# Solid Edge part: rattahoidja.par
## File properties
Author: Romil
Template: iso part.par
Last saved by: Romil
Revision: 39
Application: Solid Edge
Accuracy: 0.990
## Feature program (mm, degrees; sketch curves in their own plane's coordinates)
sketch for "unnamed Protrusion 1" plane through (0, 0, 0) normal (1, 0, 0) x-axis (0, 1, 0)
  line (14.405, 7.625) -> (-22.495, 7.625)
  line (-22.495, -7.625) -> (14.405, -7.625)
  line (14.405, -7.625) -> (26.6848, -4.0309)
  line (14.405, 7.625) -> (26.6848, 4.0309)
extrude "unnamed Protrusion 1" add finite 7.8 symmetric
sketch for "ExtrudedCutout_11" #1 plane through (0, 0, 0) normal (1, 0, 0) x-axis (0, 1, 0)
sketch for "ExtrudedCutout_11" #2 plane through (0, 0, 0) normal (1, 0, 0) x-axis (0, 1, 0)
sketch for "ExtrudedCutout_11" #3 plane through (0, 0, 0) normal (1, 0, 0) x-axis (0, 1, 0)
  line (-19.5748, 2.1053) -> (-16.4143, 3.518)
  line (-19.5748, -2.1053) -> (-16.4143, -3.518)
sketch for "ExtrudedCutout_11" #4 plane through (0, 0, 0) normal (1, 0, 0) x-axis (0, 1, 0)
  line (-16.2756, 2.78) -> (-19.2092, 1.4708)
  arc centre (-22.495, 0) radius 3.6 from (-19.2092, 1.4708) to (-19.2076, -1.4673) cw
  line (-19.2076, -1.4673) -> (-16.2754, -2.78)
  line (-16.0435, -2.78) -> (-16.2754, -2.78)
  arc centre (-22.495, 0) radius 7.025 from (-16.0435, 2.78) to (-16.0435, -2.78) cw
  line (-16.0435, 2.78) -> (-16.2756, 2.78)
sketch for "ExtrudedCutout_11" #5 plane through (0, 0, 0) normal (1, 0, 0) x-axis (0, 1, 0)
  arc centre (-22.495, 0) radius 7.625 from (-15.3948, 2.78) to (-15.3948, -2.78) cw
  line (-15.3948, -2.78) -> (-13.488, -2.78)
  arc centre (-20.5881, 0) radius 7.625 from (-13.488, 2.78) to (-13.488, -2.78) cw
  line (-15.3948, 2.78) -> (-13.488, 2.78)
sketch for "ExtrudedCutout_11" #6 plane through (0, 0, 0) normal (1, 0, 0) x-axis (0, 1, 0)
  line (-11.5918, -2.4) -> (1.505, -2.4)
  line (1.505, 2.4) -> (-11.5918, 2.4)
sketch for "ExtrudedCutout_11" #7 plane through (0, 0, 0) normal (1, 0, 0) x-axis (0, 1, 0)
  line (-6.745, 3.6) -> (-14.245, 3.6)
  line (-14.245, 3.6) -> (-14.245, 7.025)
  line (-14.245, 7.025) -> (-6.745, 7.025)
  line (-6.745, 3.6) -> (-6.745, 7.025)
sketch for "ExtrudedCutout_11" #8 plane through (0, 0, 0) normal (1, 0, 0) x-axis (0, 1, 0)
  line (-14.745, 3.6) -> (-15.7733, 3.6)
  arc centre (-22.495, 0) radius 7.625 from (-19.5302, 7.025) to (-15.7733, 3.6) cw
  line (-19.5302, 7.025) -> (-14.745, 7.025)
  line (-14.745, 7.025) -> (-14.745, 3.6)
sketch for "ExtrudedCutout_11" #9 plane through (0, 0, 0) normal (1, 0, 0) x-axis (0, 1, 0)
  line (1.255, 3.6) -> (-6.245, 3.6)
  line (-6.245, 7.025) -> (-6.245, 3.6)
  line (-6.245, 7.025) -> (1.255, 7.025)
  line (1.255, 3.6) -> (1.255, 7.025)
sketch for "ExtrudedCutout_11" #10 plane through (0, 0, 0) normal (1, 0, 0) x-axis (0, 1, 0)
  line (9.255, 3.6) -> (1.755, 3.6)
  line (1.755, 7.025) -> (1.755, 3.6)
  line (1.755, 7.025) -> (9.255, 7.025)
  line (9.255, 3.6) -> (9.255, 7.025)
sketch for "ExtrudedCutout_11" #11 plane through (0, 0, 0) normal (1, 0, 0) x-axis (0, 1, 0)
  line (17.255, 3.6) -> (9.755, 3.6)
  line (9.755, 7.025) -> (9.755, 3.6)
  line (9.755, 7.025) -> (14.405, 7.025)
  line (14.405, 7.025) -> (17.255, 6.1849)
  line (17.255, 3.6) -> (17.255, 6.1849)
sketch for "ExtrudedCutout_11" #12 plane through (0, 0, 0) normal (1, 0, 0) x-axis (0, 1, 0)
  line (17.755, 3.6) -> (25.255, 3.6)
  line (25.255, 3.8268) -> (25.255, 3.6)
  line (17.755, 6.0376) -> (25.255, 3.8268)
  line (17.755, 6.0376) -> (17.755, 3.6)
sketch for "ExtrudedCutout_11" #13 plane through (0, 0, 0) normal (1, 0, 0) x-axis (0, 1, 0)
  arc centre (24.53, 0.975) radius 0.1 from (24.63, 0.975) to (24.53, 0.875) cw
  line (24.53, 0.875) -> (23.4601, 0.875)
  line (23.4601, 0.875) -> (22.4213, 0.875)
  arc centre (22.4213, 1.175) radius 0.3 from (22.1409, 1.2818) to (22.4213, 0.875) ccw
  arc centre (25.505, 0) radius 3.6 from (22.1409, 1.2818) to (22.7266, 2.2892) cw
  arc centre (22.4951, 2.48) radius 0.3 from (22.7266, 2.2892) to (22.4951, 2.78) ccw
  line (20.5552, 2.78) -> (22.4951, 2.78)
  arc centre (20.5552, 2.48) radius 0.3 from (20.5552, 2.78) to (20.3237, 2.2892) ccw
  arc centre (20.5552, -2.48) radius 0.3 from (20.3237, -2.2892) to (20.5552, -2.78) ccw
  line (20.5552, -2.78) -> (22.4951, -2.78)
  arc centre (22.4951, -2.48) radius 0.3 from (22.4951, -2.78) to (22.7266, -2.2892) ccw
  arc centre (25.505, 0) radius 3.6 from (22.7266, -2.2892) to (22.1409, -1.2818) cw
  arc centre (22.4213, -1.175) radius 0.3 from (22.4213, -0.875) to (22.1409, -1.2818) ccw
  line (22.4213, -0.875) -> (23.4601, -0.875)
  line (23.4601, -0.875) -> (24.53, -0.875)
  arc centre (24.53, -0.975) radius 0.1 from (24.53, -0.875) to (24.63, -0.975) cw
  line (24.63, -0.975) -> (24.63, -2.0449)
  line (24.63, -2.0449) -> (24.63, -2.181)
  arc centre (25.505, 0) radius 2.35 from (24.63, -2.181) to (26.38, -2.181) ccw
  line (26.38, -2.181) -> (26.38, -2.0449)
  line (26.38, -2.0449) -> (26.38, -0.975)
  arc centre (26.48, -0.975) radius 0.1 from (26.38, -0.975) to (26.48, -0.875) cw
  line (26.48, -0.875) -> (27.5499, -0.875)
  line (27.5499, -0.875) -> (27.686, -0.875)
  arc centre (25.505, 0) radius 2.35 from (27.686, -0.875) to (27.686, 0.875) ccw
  line (27.686, 0.875) -> (27.5499, 0.875)
  line (27.5499, 0.875) -> (26.48, 0.875)
  arc centre (26.48, 0.975) radius 0.1 from (26.48, 0.875) to (26.38, 0.975) cw
  line (26.38, 0.975) -> (26.38, 2.0449)
  line (26.38, 2.0449) -> (26.38, 2.181)
  arc centre (25.505, 0) radius 2.35 from (26.38, 2.181) to (24.63, 2.181) ccw
  line (24.63, 2.181) -> (24.63, 2.0449)
  line (24.63, 2.0449) -> (24.63, 0.975)
sketch for "ExtrudedCutout_11" #14 plane through (0, 0, 0) normal (1, 0, 0) x-axis (0, 1, 0)
  circle centre (17.505, 0) radius 2.4
sketch for "ExtrudedCutout_11" #15 plane through (0, 0, 0) normal (1, 0, 0) x-axis (0, 1, 0)
  arc centre (17.5453, 0) radius 3.6 from (14.7669, -2.2892) to (14.7669, 2.2892) cw
  arc centre (14.5354, 2.48) radius 0.3 from (14.7669, 2.2892) to (14.5354, 2.78) ccw
  line (12.5149, 2.78) -> (14.5354, 2.78)
  arc centre (12.5149, 2.48) radius 0.3 from (12.5149, 2.78) to (12.2834, 2.2892) ccw
  arc centre (9.505, 0) radius 3.6 from (12.2834, 2.2892) to (12.8691, 1.2818) cw
  arc centre (12.5887, 1.175) radius 0.3 from (12.5887, 0.875) to (12.8691, 1.2818) ccw
  line (12.5887, 0.875) -> (11.5499, 0.875)
  line (11.5499, 0.875) -> (10.48, 0.875)
  arc centre (10.48, 0.975) radius 0.1 from (10.48, 0.875) to (10.38, 0.975) cw
  line (10.38, 0.975) -> (10.38, 2.0449)
  line (10.38, 2.0449) -> (10.38, 2.181)
  arc centre (9.505, 0) radius 2.35 from (10.38, 2.181) to (8.63, 2.181) ccw
  line (8.63, 2.181) -> (8.63, 2.0449)
  line (8.63, 2.0449) -> (8.63, 0.975)
  arc centre (8.53, 0.975) radius 0.1 from (8.63, 0.975) to (8.53, 0.875) cw
  line (8.53, 0.875) -> (7.4601, 0.875)
  line (7.4601, 0.875) -> (7.324, 0.875)
  arc centre (9.505, 0) radius 2.35 from (7.324, 0.875) to (7.324, -0.875) ccw
  line (7.324, -0.875) -> (7.4601, -0.875)
  line (7.4601, -0.875) -> (8.53, -0.875)
  arc centre (8.53, -0.975) radius 0.1 from (8.53, -0.875) to (8.63, -0.975) cw
  line (8.63, -0.975) -> (8.63, -2.0449)
  line (8.63, -2.0449) -> (8.63, -2.181)
  arc centre (9.505, 0) radius 2.35 from (8.63, -2.181) to (10.38, -2.181) ccw
  line (10.38, -2.181) -> (10.38, -2.0449)
  line (10.38, -2.0449) -> (10.38, -0.975)
  arc centre (10.48, -0.975) radius 0.1 from (10.38, -0.975) to (10.48, -0.875) cw
  line (10.48, -0.875) -> (11.5499, -0.875)
  line (11.5499, -0.875) -> (12.5887, -0.875)
  arc centre (12.5887, -1.175) radius 0.3 from (12.8691, -1.2818) to (12.5887, -0.875) ccw
  arc centre (9.505, 0) radius 3.6 from (12.8691, -1.2818) to (12.2834, -2.2892) cw
  arc centre (12.5149, -2.48) radius 0.3 from (12.2834, -2.2892) to (12.5149, -2.78) ccw
  line (12.5149, -2.78) -> (14.5354, -2.78)
  arc centre (14.5354, -2.48) radius 0.3 from (14.5354, -2.78) to (14.7669, -2.2892) ccw
sketch for "ExtrudedCutout_11" #16 plane through (0, 0, 0) normal (1, 0, 0) x-axis (0, 1, 0)
  arc centre (6.4951, 2.48) radius 0.3 from (6.7266, 2.2892) to (6.4951, 2.78) ccw
  line (6.4951, 2.78) -> (4.5149, 2.78)
  arc centre (4.5149, 2.48) radius 0.3 from (4.5149, 2.78) to (4.2834, 2.2892) ccw
  arc centre (4.5149, -2.48) radius 0.3 from (4.2834, -2.2892) to (4.5149, -2.78) ccw
  line (6.4951, -2.78) -> (4.5149, -2.78)
  arc centre (6.4951, -2.48) radius 0.3 from (6.4951, -2.78) to (6.7266, -2.2892) ccw
sketch for "ExtrudedCutout_11" #17 plane through (0, 0, 0) normal (1, 0, 0) x-axis (0, 1, 0)
  line (9.255, -7.025) -> (9.255, -3.6)
  line (1.755, -3.6) -> (9.255, -3.6)
  line (1.755, -3.6) -> (1.755, -7.025)
  line (1.755, -7.025) -> (9.255, -7.025)
sketch for "ExtrudedCutout_11" #18 plane through (0, 0, 0) normal (1, 0, 0) x-axis (0, 1, 0)
  line (9.755, -3.6) -> (17.255, -3.6)
  line (17.255, -6.1849) -> (17.255, -3.6)
  line (14.405, -7.025) -> (17.255, -6.1849)
  line (9.755, -7.025) -> (14.405, -7.025)
  line (9.755, -3.6) -> (9.755, -7.025)
sketch for "ExtrudedCutout_11" #19 plane through (0, 0, 0) normal (1, 0, 0) x-axis (0, 1, 0)
  line (17.755, -3.6) -> (25.255, -3.6)
  line (25.255, -3.6) -> (25.255, -3.8268)
  line (17.755, -6.0376) -> (25.255, -3.8268)
  line (17.755, -3.6) -> (17.755, -6.0376)
sketch for "ExtrudedCutout_11" #20 plane through (0, 0, 0) normal (1, 0, 0) x-axis (0, 1, 0)
  line (-6.245, -3.6) -> (1.255, -3.6)
  line (1.255, -7.025) -> (1.255, -3.6)
  line (-6.245, -7.025) -> (1.255, -7.025)
  line (-6.245, -3.6) -> (-6.245, -7.025)
sketch for "ExtrudedCutout_11" #21 plane through (0, 0, 0) normal (1, 0, 0) x-axis (0, 1, 0)
  line (-14.245, -3.6) -> (-6.745, -3.6)
  line (-6.745, -7.025) -> (-6.745, -3.6)
  line (-14.245, -7.025) -> (-6.745, -7.025)
  line (-14.245, -7.025) -> (-14.245, -3.6)
extrude "ExtrudedCutout_11" cut finite 12.3726 symmetric
sketch for "ExtrudedCutout_12" plane through (3.9, -0.2075, 0) normal (1, 0, 0) x-axis (0, 1, 0)
  line (14.6125, -7.025) -> (-14.5375, -7.025)
  line (-14.5375, -7.025) -> (-14.5375, -3.6)
  line (-14.5375, -3.6) -> (-15.5658, -3.6)
  line (-15.5658, -3.6) -> (-16.0293, -3.6)
  line (-16.0293, -3.6) -> (-16.2068, -3.518)
  line (-19.3673, -2.1053) -> (-16.2068, -3.518)
  arc centre (-22.2875, 0) radius 3.6 from (-19.3673, 2.1053) to (-19.3673, -2.1053) ccw
  line (-16.2068, 3.518) -> (-19.3673, 2.1053)
  line (-16.2068, 3.518) -> (-16.0116, 3.6)
  line (-16.0116, 3.6) -> (-15.5658, 3.6)
  line (-15.5658, 3.6) -> (-14.5375, 3.6)
  line (-14.5375, 3.6) -> (-14.5375, 7.025)
  line (-14.5375, 7.025) -> (14.6125, 7.025)
  line (14.6125, 7.025) -> (25.4625, 3.8268)
  line (25.4625, 3.8268) -> (25.4625, 3.6)
  line (25.4625, 3.6) -> (25.7125, 3.6)
  arc centre (25.7125, 0) radius 3.6 from (25.7125, 3.6) to (25.7125, -3.6) cw
  line (25.4625, -3.6) -> (25.7125, -3.6)
  line (25.4625, -3.6) -> (25.4625, -3.8268)
  line (25.4625, -3.8268) -> (14.6125, -7.025)
extrude "ExtrudedCutout_12" cut finite 2.2 along -normal
sketch for "ExtrudedCutout_13" plane through (3.9, 1.505, 0) normal (1, 0, 0) x-axis (0, -0.959198, -0.282737)
  arc centre (23.0207, -6.7857) radius 7.025 from (16.0464, -7.6282) to (17.6185, -2.295) cw
  line (17.6185, -2.295) -> (16.9963, -2.1116)
  arc centre (23.0207, -6.7857) radius 7.625 from (15.4243, -7.4448) to (16.9963, -2.1116) cw
  line (16.0464, -7.6282) -> (15.4243, -7.4448)
extrude "ExtrudedCutout_13" cut finite 2.2 along -normal
sketch for "ExtrudedCutout_16" plane through (0, 0, 0) normal (0, -1, 0) x-axis (1, 0, 0)
  line (5.8336, 3.6) -> (5.8336, 7.025)
  line (5.8336, 7.025) -> (1.7, 7.025)
  line (1.7, 7.025) -> (2.9, 3.6)
  line (2.9, 3.6) -> (5.8336, 3.6)
extrude "ExtrudedCutout_16" cut finite 74.1361 symmetric
sketch for "unnamed Cutout 1" plane through (3.9, 22.4445, 3.6) normal (0, 1, 0) x-axis (1, 0, 0)
  line (-1, 0) -> (-2.2, -2.4376)
  line (-2.2, -2.4376) -> (-2.2, -4.2265)
  line (-2.2, -4.2265) -> (0, -2.4376)
  line (0, -2.4376) -> (0, 0)
  line (0, 0) -> (-1, 0)
extrude "unnamed Cutout 1" cut to key point symmetric
mirror "unnamed Mirror 1" of "ExtrudedCutout_16", "unnamed Cutout 1" about plane through (0, 0, 0) normal (0, 0, 1)
extrude "unnamed Cutout 2" cut finite 74.1361 symmetric
extrude "unnamed Cutout 3" cut finite 10.379 symmetric
sketch for "ExtrudedCutout_22" #1 plane through (3.9, -0.2075, 0) normal (1, 0, 0) x-axis (0, 1, 0)
  arc centre (-19.4218, 0) radius 7.625 from (-12.4554, 3.1) to (-12.4554, -3.1) cw
  line (1.7125, -3.1) -> (-12.4554, -3.1)
  arc centre (1.7125, 0) radius 3.1 from (1.7125, 3.1) to (1.7125, -3.1) cw
  line (-12.4554, 3.1) -> (1.7125, 3.1)
sketch for "ExtrudedCutout_22" #2 plane through (3.9, -0.2075, 0) normal (1, 0, 0) x-axis (0, 1, 0)
  circle centre (17.7125, 0) radius 3.1
extrude "ExtrudedCutout_22" cut finite 0.9 along -normal
mirror "unnamed Mirror 2" of "ExtrudedCutout_12", "ExtrudedCutout_13", "ExtrudedCutout_16", "unnamed Mirror 1", "ExtrudedCutout_22", "unnamed Cutout 1" about plane through (0, 0, 0) normal (1, 0, 0)
extrude "unnamed Cutout 4" cut finite 2.2
extrude "unnamed Cutout 5" cut finite 2.2
extrude "unnamed Cutout 6" cut finite 74.1361 symmetric
extrude "unnamed Cutout 7" cut finite 10.379 symmetric
extrude "unnamed Cutout 8" cut finite 74.1361 symmetric
extrude "unnamed Cutout 9" cut finite 10.379 symmetric
extrude "unnamed Cutout 10" cut finite 0.9
sketch for "ExtrudedProtrusion_3" plane through (0, -12.0559, 0) normal (0, -1, 0) x-axis (1, 0, 0)
  circle centre (0, 0) radius 0.6
extrude "ExtrudedProtrusion_3" add finite 12.1 along -normal
sketch for "ExtrudedProtrusion_4" plane through (0, -6.0269, 0) normal (0, -1, 0) x-axis (1, 0, 0)
  circle centre (0, 0) radius 1.1543
extrude "ExtrudedProtrusion_4" add finite 1.2 along -normal
sketch for "ExtrudedProtrusion_5" plane through (0, -6.0269, 0) normal (0, -1, 0) x-axis (1, 0, 0)
  line (-0.7868, -0.3584) -> (-0.7868, 0.3584)
  arc centre (-0.3868, 0.3584) radius 0.4 from (-0.6802, 0.6302) to (-0.7868, 0.3584) ccw
  arc centre (0, 0) radius 0.9273 from (-0.6802, 0.6302) to (0.6802, 0.6302) cw
  arc centre (0.3868, 0.3584) radius 0.4 from (0.7868, 0.3584) to (0.6802, 0.6302) ccw
  line (0.7868, 0.3584) -> (0.7868, -0.3584)
  arc centre (0.3868, -0.3584) radius 0.4 from (0.6802, -0.6302) to (0.7868, -0.3584) ccw
  arc centre (-0.3868, -0.3584) radius 0.4 from (-0.7868, -0.3584) to (-0.6802, -0.6302) ccw
extrude "ExtrudedProtrusion_5" add finite 5.8 along -normal
sketch for "ExtrudedProtrusion_6" plane through (0, -0.2269, 0) normal (0, 1, 0) x-axis (0, 0, 1)
  circle centre (0, 0) radius 1.1543
extrude "ExtrudedProtrusion_6" add finite 1.2 along -normal
sketch for "unnamed Protrusion 2" plane through (0, 0, 0) normal (1, 0, 0) x-axis (0, 1, 0)
  circle centre (1.505, 0) radius 1.6653
extrude "unnamed Protrusion 2" add finite 3.1635 symmetric
sketch for "ExtrudedProtrusion_11" plane through (0, 0.5843, 0) normal (0, -1, 0) x-axis (1, 0, 0)
  line (-0.5, 3.518) -> (-0.5, -3.518)
  line (-0.5, -3.518) -> (0.5, -3.518)
  line (0.5, -3.518) -> (0.5, 3.518)
  line (0.5, 3.518) -> (-0.5, 3.518)
extrude "ExtrudedProtrusion_11" add finite 6.3049 along -normal
sketch for "unnamed Cutout 11" plane through (-1.5818, 1.505, 0) normal (-1, 0, 0) x-axis (0, -1, 0)
  circle centre (0, 0) radius 1.2264
extrude "unnamed Cutout 11" cut finite 0.3534 along -normal
fillet "Round_7" radius 0.4
mirror "unnamed Mirror 3" of "Round_7", "unnamed Cutout 11" about plane through (0, 0, 0) normal (1, 0, 0)
extrude "unnamed Cutout 12" cut finite 0.3534
fillet "unnamed Round 1"
swept cutout "SweptCutout_4"
sketch for "unnamed Protrusion 3" plane through (0, 0, 0) normal (1, 0, 0) x-axis (0, 1, 0)
  circle centre (-22.495, 0) radius 7.025
extrude "unnamed Protrusion 3" add to key point symmetric
helix cutout "HelixCutout_6"  NumberOfTurns = 0.33
pattern "unnamed Pattern 1" of "HelixCutout_6"
helix cutout "unnamed HelixCutout 1"
helix cutout "unnamed HelixCutout 2"
helix cutout "unnamed HelixCutout 3"
helix cutout "unnamed HelixCutout 4"
helix cutout "unnamed HelixCutout 5"
swept cutout "SweptCutout_7"
mirror "unnamed Mirror 4" of "SweptCutout_7" about plane through (0, 0, 0) normal (1, 0, 0)
swept cutout "unnamed SweptCutout 1"
sketch for "ExtrudedCutout_35" plane through (0, 0, 0) normal (1, 0, 0) x-axis (0, 1, 0)
  arc centre (-24.2981, 1.8031) radius 0.9025 from (-23.3956, 1.8031) to (-24.2981, 0.9006) cw
  line (-24.2981, 0.9006) -> (-24.8807, 0.9006)
  arc centre (-22.495, 0) radius 2.55 from (-24.4011, -1.6939) to (-24.8807, 0.9006) cw
  line (-24.4011, -1.6939) -> (-23.7678, -1.0607)
  arc centre (-23.6617, -1.1667) radius 0.15 from (-23.7678, -1.0607) to (-23.5557, -1.2728) cw
  line (-23.5557, -1.2728) -> (-24.1889, -1.9061)
  arc centre (-22.495, 0) radius 2.55 from (-21.5944, -2.3857) to (-24.1889, -1.9061) cw
  line (-21.5944, -2.3857) -> (-21.5944, -1.8031)
  arc centre (-20.6919, -1.8031) radius 0.9025 from (-21.5944, -1.8031) to (-20.6919, -0.9006) cw
  line (-20.6919, -0.9006) -> (-20.1093, -0.9006)
  arc centre (-22.495, 0) radius 2.55 from (-20.5889, 1.6939) to (-20.1093, -0.9006) cw
  line (-20.5889, 1.6939) -> (-21.2222, 1.0607)
  arc centre (-21.3283, 1.1667) radius 0.15 from (-21.2222, 1.0607) to (-21.4343, 1.2728) cw
  line (-21.4343, 1.2728) -> (-20.8011, 1.9061)
  arc centre (-22.495, 0) radius 2.55 from (-23.3956, 2.3857) to (-20.8011, 1.9061) cw
  line (-23.3956, 2.3857) -> (-23.3956, 1.8031)
extrude "ExtrudedCutout_35" cut finite 765.3177 symmetric
sketch for "unnamed Protrusion 4" #1 plane through (0, 0, 0) normal (1, 0, 0) x-axis (0, 1, 0)
  line (-19.5748, 2.1053) -> (-16.4143, 3.518)
  line (-16.0435, 2.78) -> (-16.2756, 2.78)
  line (-16.2756, 2.78) -> (-19.2092, 1.4708)
  arc centre (-22.495, 0) radius 3.6 from (-19.5748, 2.1053) to (-19.2092, 1.4708) cw
sketch for "unnamed Protrusion 4" #2 plane through (0, 0, 0) normal (1, 0, 0) x-axis (0, 1, 0)
  line (-19.2076, -1.4673) -> (-16.2754, -2.78)
  line (-16.0435, -2.78) -> (-16.2754, -2.78)
  arc centre (-22.495, 0) radius 7.025 from (-16.4143, -3.518) to (-16.0435, -2.78) ccw
  line (-19.5748, -2.1053) -> (-16.4143, -3.518)
extrude "unnamed Protrusion 4" add to key point symmetric
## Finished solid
Body 1: solid body, 253 faces, 706 edges, 436 vertices.
  Faces by surface: plane 132, cylinder 93, cone 12, spline 12, torus 4
  Edges by curve: line 436, circle 214, intersection 30, spline 24, ellipse 2
Bounding box of the edges (mm; curved faces can reach further): 7.800 x 59.328 x 15.137, from (-3.9, -29.8716, -7.5685) to (3.9, 29.4566, 7.5685).
Cylindrical faces by radius (mm): R0.1 x8, R0.15 x2, R0.3 x20, R0.4 x4, R0.6 x2, R0.9025 x2, R0.9273 x2, R1.1543 x2, R1.6653 x1, R2.35 x6, R2.4 x3, R2.55 x4, R3.1 x4, R3.6 x14, R7.025 x8, R7.625 x11
Conical faces (half-angle, radius in mm at the cone's reference point): 70.6913 deg R3.6 x6, 70.6913 deg R7.025 x6
Toroidal faces (ring radius, tube radius in mm): R-3.4815 r7.625 x1, R-0.0565 r7.625 x1, R1.6237 r0.4 x2
Planar faces by outward normal: +x 10, +y 17, +z 19, -x 10, -y 21, -z 19, oblique 36
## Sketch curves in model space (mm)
line (0, -15.3948, -2.78) -> (0, -15.3938, -2.78)
arc centre (0, -22.495, 0) radius 7.025 from (0, -16.0435, 2.78) through (0, -16.218, 3.1544) to (0, -16.4143, 3.518)
line (0, -16.0435, 2.78) -> (0, -16.2756, 2.78)
line (0, -16.2756, 2.78) -> (0, -19.2092, 1.4708)
arc centre (0, -22.495, 0) radius 3.6 from (0, -19.5748, 2.1053) through (0, -19.3758, 1.7974) to (0, -19.2092, 1.4708)
line (0, -19.5748, 2.1053) -> (0, -16.4143, 3.518)
line (0, -16.0435, -2.78) -> (0, -16.2754, -2.78)
arc centre (0, -22.495, 0) radius 7.025 from (0, -16.4143, -3.518) through (0, -16.218, -3.1544) to (0, -16.0435, -2.78)
line (0, -19.5748, -2.1053) -> (0, -16.4143, -3.518)
arc centre (0, -22.495, 0) radius 3.6 from (0, -19.2076, -1.4673) through (0, -19.3748, -1.7957) to (0, -19.5748, -2.1053)
line (0, -19.2076, -1.4673) -> (0, -16.2754, -2.78)
circle centre (3.9, -22.495, 0) radius 3.6
line (4.7757, -29.3325, 0) -> (4.7757, -26.095, 0)
line (4.7757, -29.52, 0) -> (4.7757, -29.3325, 0)
line (1.7, -29.52, 0) -> (4.7757, -29.52, 0)
line (1.7, -29.52, 0) -> (2.9, -26.095, 0)
line (3.9, -26.095, 0) -> (2.9, -26.095, 0)
line (3.9, -26.095, 0) -> (4.7757, -26.095, 0)
line (3.9, -22.495, 0) -> (-11.7, -22.495, 0)
line (4.9121, -22.495, 3.7145) -> (4.9121, -22.495, 3.6)
line (11.3, -22.495, 3.6) -> (4.9121, -22.495, 3.6)
line (11.3, -22.495, 7.025) -> (11.3, -22.495, 3.6)
line (3.9, -22.495, 7.025) -> (11.3, -22.495, 7.025)
line (3.9, -22.495, 7.025) -> (3.9, -22.495, 3.6)
line (4.9121, -22.495, 3.6) -> (3.9, -22.495, 3.6)
circle centre (0, -22.495, 0) radius 7.025
circle centre (0, -22.495, 0) radius 2.55
circle centre (0, -22.495, 0) radius 3.6
circle centre (0, -22.495, 0) radius 7.625
line (0.5, 0.5843, -3.518) -> (0.5, 0.5843, 3.518)
line (0.5, 0.5843, 3.518) -> (-0.5, 0.5843, 3.518)
line (-0.5, 0.5843, 3.518) -> (-0.5, 0.5843, -3.518)
line (-0.5, 0.5843, -3.518) -> (0.5, 0.5843, -3.518)
circle centre (-1.5818, 1.505, 0) radius 1.2264
circle centre (0, 1.505, 0) radius 1.6653
arc centre (0, -22.4385, 0) radius 7.625 from (1.7, -29.8716, 0) through (0, -30.0635, 0) to (-1.7, -29.8716, 0)
line (1.7, -30.0635, 0) -> (1.7, -29.8716, 0)
line (1.7, -30.12, 0) -> (1.7, -30.0635, 0)
line (-1.7, -30.12, 0) -> (1.7, -30.12, 0)
line (-1.7, -30.0635, 0) -> (-1.7, -30.12, 0)
line (-1.7, -30.0635, 0) -> (-1.7, -29.8716, 0)
circle centre (0, -0.2269, 0) radius 1.1543
circle centre (0, -6.0269, 0) radius 1.1543
arc centre (0.3868, -6.0269, -0.3584) radius 0.4 from (0.6802, -6.0269, -0.6302) through (0.7592, -6.0269, -0.5044) to (0.7868, -6.0269, -0.3584)
arc centre (0, -6.0269, 0) radius 0.9273 from (0.6802, -6.0269, -0.6302) through (0, -6.0269, -0.9273) to (-0.6802, -6.0269, -0.6302)
arc centre (-0.3868, -6.0269, -0.3584) radius 0.4 from (-0.7868, -6.0269, -0.3584) through (-0.7592, -6.0269, -0.5044) to (-0.6802, -6.0269, -0.6302)
line (-0.7868, -6.0269, -0.3584) -> (-0.7868, -6.0269, 0.3584)
arc centre (-0.3868, -6.0269, 0.3584) radius 0.4 from (-0.6802, -6.0269, 0.6302) through (-0.7592, -6.0269, 0.5044) to (-0.7868, -6.0269, 0.3584)
arc centre (0, -6.0269, 0) radius 0.9273 from (-0.6802, -6.0269, 0.6302) through (0, -6.0269, 0.9273) to (0.6802, -6.0269, 0.6302)
arc centre (0.3868, -6.0269, 0.3584) radius 0.4 from (0.7868, -6.0269, 0.3584) through (0.7592, -6.0269, 0.5044) to (0.6802, -6.0269, 0.6302)
line (0.7868, -6.0269, 0.3584) -> (0.7868, -6.0269, -0.3584)
circle centre (0, -12.0559, 0) radius 0.6
line (2.9, 22.4445, 3.6) -> (1.7, 22.4445, 6.0376)
line (1.7, 22.4445, 6.0376) -> (1.7, 22.4445, 7.8265)
line (1.7, 22.4445, 7.8265) -> (3.9, 22.4445, 6.0376)
line (3.9, 22.4445, 6.0376) -> (3.9, 22.4445, 3.6)
line (3.9, 22.4445, 3.6) -> (2.9, 22.4445, 3.6)
line (3.9, 0, 4.9946) -> (3.9, 0, 3.6)
line (2.9, 0, 3.6) -> (5.8336, 0, 3.6)
line (5.8336, 0, 3.6) -> (5.8336, 0, 7.025)
line (5.8336, 0, 7.025) -> (1.7, 0, 7.025)
line (1.7, 0, 7.025) -> (2.9, 0, 3.6)
line (3.9, -16.0435, -2.78) -> (3.9, -15.3948, -2.78)
arc centre (3.9, -22.495, 0) radius 7.625 from (3.9, -15.3948, 2.78) through (3.9, -14.87, 0) to (3.9, -15.3948, -2.78)
line (3.9, -16.0435, 2.78) -> (3.9, -15.3948, 2.78)
arc centre (3.9, -22.495, 0) radius 7.025 from (3.9, -16.0435, 2.78) through (3.9, -15.47, 0) to (3.9, -16.0435, -2.78)
circle centre (3.9, 17.505, 0) radius 3.1
line (3.9, -19.5748, -2.1053) -> (3.9, -16.4143, -3.518)
line (3.9, -16.2368, -3.6) -> (3.9, -16.4143, -3.518)
line (3.9, -15.7733, -3.6) -> (3.9, -16.2368, -3.6)
line (3.9, -14.745, -3.6) -> (3.9, -15.7733, -3.6)
line (3.9, -14.745, -7.025) -> (3.9, -14.745, -3.6)
line (3.9, 14.405, -7.025) -> (3.9, -14.745, -7.025)
line (3.9, 25.255, -3.8268) -> (3.9, 14.405, -7.025)
line (3.9, 25.255, -3.6) -> (3.9, 25.255, -3.8268)
line (3.9, 25.255, -3.6) -> (3.9, 25.505, -3.6)
arc centre (3.9, 25.505, 0) radius 3.6 from (3.9, 25.505, 3.6) through (3.9, 29.1034, -0.1067) to (3.9, 25.505, -3.6)
line (3.9, 25.255, 3.6) -> (3.9, 25.505, 3.6)
line (3.9, 25.255, 3.8268) -> (3.9, 25.255, 3.6)
line (3.9, 14.405, 7.025) -> (3.9, 25.255, 3.8268)
line (3.9, -14.745, 7.025) -> (3.9, 14.405, 7.025)
line (3.9, -14.745, 3.6) -> (3.9, -14.745, 7.025)
line (3.9, -15.7733, 3.6) -> (3.9, -14.745, 3.6)
line (3.9, -16.2191, 3.6) -> (3.9, -15.7733, 3.6)
line (3.9, -16.4143, 3.518) -> (3.9, -16.2191, 3.6)
line (3.9, -16.4143, 3.518) -> (3.9, -19.5748, 2.1053)
arc centre (3.9, -22.495, 0) radius 3.6 from (3.9, -19.5748, 2.1053) through (3.9, -26.0934, -0.1079) to (3.9, -19.5748, -2.1053)
line (3.9, 1.505, -3.1) -> (3.9, -12.6629, -3.1)
arc centre (3.9, 1.505, 0) radius 3.1 from (3.9, 1.505, 3.1) through (3.9, 4.6036, -0.0919) to (3.9, 1.505, -3.1)
line (3.9, -12.6629, 3.1) -> (3.9, 1.505, 3.1)
arc centre (3.9, -19.6293, 0) radius 7.625 from (3.9, -12.6629, 3.1) through (3.9, -12.0043, 0) to (3.9, -12.6629, -3.1)
circle centre (0, 17.505, 0) radius 3.1
circle centre (0, 17.505, 0) radius 2.4
line (0, -14.245, 7.625) -> (0, -14.745, 7.625)
line (0, -14.745, -7.625) -> (0, -14.245, -7.625)
line (0, -6.245, -7.625) -> (0, -6.745, -7.625)
line (0, -6.745, 7.625) -> (0, -6.245, 7.625)
line (0, -12.3545, -7.625) -> (0, -11.8545, -7.625)
line (0, -4.3545, -7.625) -> (0, -3.8545, -7.625)
line (0, 1.755, -7.625) -> (0, 1.255, -7.625)
line (0, 1.255, 7.625) -> (0, 1.755, 7.625)
line (0, 9.755, -7.625) -> (0, 9.255, -7.625)
line (0, 9.255, 7.625) -> (0, 9.755, 7.625)
arc centre (0, -22.495, 0) radius 2.55 from (0, -25.0406, 0.15) through (0, -24.989, 0.5314) to (0, -24.8807, 0.9006)
line (0, 14.405, -7.625) -> (0, 26.6848, -4.0309)
arc centre (0, 25.505, 0) radius 4.2 from (0, 26.6848, 4.0309) through (0, 29.6975, -0.2511) to (0, 26.6848, -4.0309)
line (0, 14.405, 7.625) -> (0, 26.6848, 4.0309)
line (0, 14.405, 7.625) -> (0, -22.495, 7.625)
arc centre (0, -22.495, 0) radius 7.625 from (0, -22.495, -7.625) through (0, -30.1167, 0.226) to (0, -22.495, 7.625)
line (0, -22.495, -7.625) -> (0, 14.405, -7.625)
arc centre (0, 24.53, 0.975) radius 0.1 from (0, 24.63, 0.975) through (0, 24.5986, 0.9023) to (0, 24.53, 0.875)
line (0, 24.53, 0.875) -> (0, 23.4601, 0.875)
line (0, 23.4601, 0.875) -> (0, 22.4213, 0.875)
arc centre (0, 22.4213, 1.175) radius 0.3 from (0, 22.1409, 1.2818) through (0, 22.1793, 0.9976) to (0, 22.4213, 0.875)
arc centre (0, 25.505, 0) radius 3.6 from (0, 22.1409, 1.2818) through (0, 22.3927, 1.8094) to (0, 22.7266, 2.2892)
arc centre (0, 22.4951, 2.48) radius 0.3 from (0, 22.7266, 2.2892) through (0, 22.7664, 2.608) to (0, 22.4951, 2.78)
line (0, 20.5552, 2.78) -> (0, 22.4951, 2.78)
arc centre (0, 20.5552, 2.48) radius 0.3 from (0, 20.5552, 2.78) through (0, 20.2839, 2.608) to (0, 20.3237, 2.2892)
arc centre (0, 17.5453, 0) radius 3.6 from (0, 20.3237, 2.2892) through (0, 21.1437, -0.1079) to (0, 20.3237, -2.2892)
arc centre (0, 20.5552, -2.48) radius 0.3 from (0, 20.3237, -2.2892) through (0, 20.2839, -2.608) to (0, 20.5552, -2.78)
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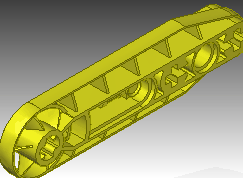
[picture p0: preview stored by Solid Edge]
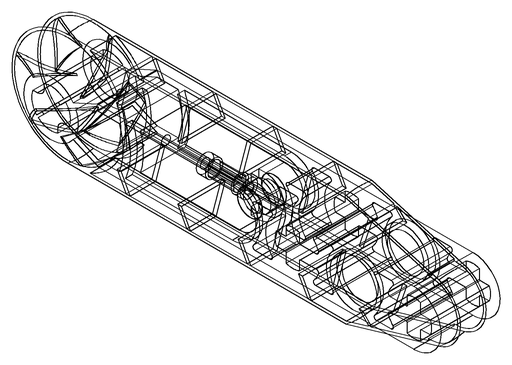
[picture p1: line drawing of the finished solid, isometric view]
